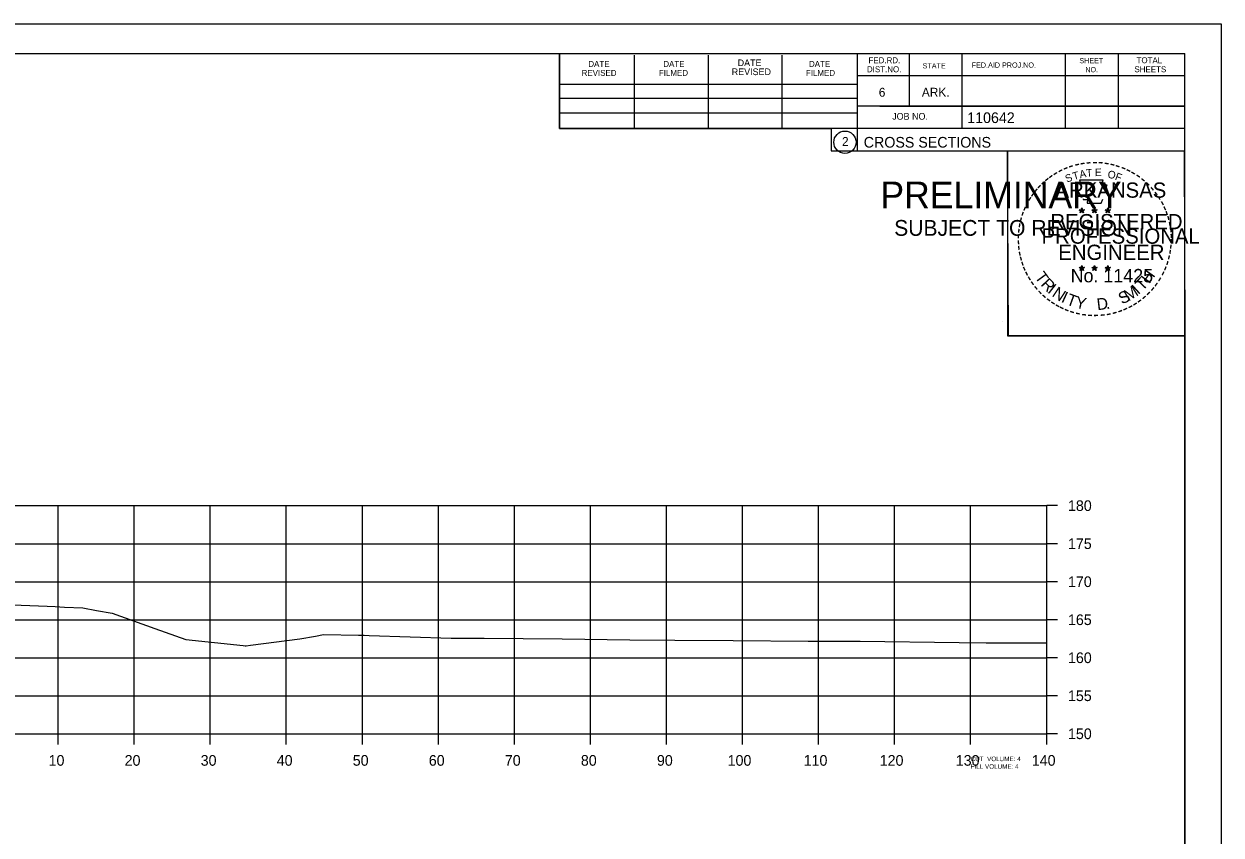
# Model space of a CAD drawing. Extents: x 1368503 to 1373085, y 379840 to 381833.
# Drawn here: x 1368678.6 to 1368836, y 381512.7 to 381619.4 of the extents above; entities that cross this region are included whole.
import ezdxf

# ---------------------------------------------------------------- set-up
doc = ezdxf.new("R2010")
doc.units = 0
for name, color, linetype in [('S_BRIDGE', 7, 'Continuous'), ('S_EDGE_PAVEMENT', 7, 'Continuous'), ('S_LANDSCAPING', 7, 'Continuous'), ('S_MISC_BOUNDARY', 7, 'Continuous'), ('S_MISC_BOUNDARY_ANNOT', 7, 'Continuous'), ('S_PHOTO_CENTERS', 7, 'Continuous'), ('S_PHOTO_NOTES', 7, 'Continuous'), ('S_TRAILS', 7, 'Continuous')]:
    doc.layers.add(name, color=color, linetype=linetype)

msp = doc.modelspace()

# ---------------------------------------------------------------- linework, layer by layer
at = {"layer": 'S_BRIDGE'}
for p, q in [((1368515.06, 381615.52), (1368831.24, 381615.52)), ((1368748.98, 381605.64), (1368748.98, 381615.52)), ((1368758.84, 381605.64), (1368758.84, 381615.32)), ((1368768.6, 381605.64), (1368768.6, 381615.32)), ((1368778.28, 381605.64), (1368778.28, 381615.32)), ((1368788.14, 381615.52), (1368788.14, 381602.72)), ((1368794.98, 381615.52), (1368794.98, 381608.58)), ((1368801.92, 381615.52), (1368801.92, 381605.64)), ((1368815.5, 381615.52), (1368815.5, 381605.64)), ((1368822.44, 381615.52), (1368822.44, 381605.64)), ((1368831.24, 381410.06), (1368831.24, 381615.52)), ((1368748.98, 381611.5), (1368788.14, 381611.5)), ((1368831.24, 381612.58), (1368788.14, 381612.58)), ((1368831.24, 381612.6), (1368831.24, 381612.6)), ((1368748.98, 381609.64), (1368788.14, 381609.64)), ((1368831.24, 381608.58), (1368788.14, 381608.58)), ((1368791.1, 381608.58), (1368831.24, 381608.58)), ((1368748.98, 381605.64), (1368748.98, 381607.7)), ((1368748.98, 381607.7), (1368788.14, 381607.7)), ((1368831.24, 381605.64), (1368748.98, 381605.64)), ((1368788.14, 381602.72), (1368831.24, 381602.72))]:
    msp.add_line(p, q, dxfattribs=at)
msp.add_circle((1368786.53, 381603.85), 1.47, dxfattribs=at)
at = {"layer": 'S_EDGE_PAVEMENT'}
for p, q in [((1368813.06, 381526.06), (1368813.06, 381556.06)), ((1368814.46, 381556.06), (1368813.06, 381556.06)), ((1368814.46, 381551.06), (1368813.06, 381551.06)), ((1368814.46, 381546.06), (1368813.06, 381546.06)), ((1368814.46, 381541.06), (1368813.06, 381541.06)), ((1368814.46, 381536.06), (1368813.06, 381536.06)), ((1368814.46, 381531.06), (1368813.06, 381531.06)), ((1368533.06, 381526.06), (1368813.06, 381526.06)), ((1368683.06, 381524.66), (1368683.06, 381526.06)), ((1368693.06, 381524.66), (1368693.06, 381526.06)), ((1368703.06, 381524.66), (1368703.06, 381526.06)), ((1368713.06, 381524.66), (1368713.06, 381526.06)), ((1368723.06, 381524.66), (1368723.06, 381526.06)), ((1368733.06, 381524.66), (1368733.06, 381526.06)), ((1368743.06, 381524.66), (1368743.06, 381526.06)), ((1368753.06, 381524.66), (1368753.06, 381526.06)), ((1368763.06, 381524.66), (1368763.06, 381526.06)), ((1368773.06, 381524.66), (1368773.06, 381526.06)), ((1368783.06, 381524.66), (1368783.06, 381526.06)), ((1368793.06, 381524.66), (1368793.06, 381526.06)), ((1368803.06, 381524.66), (1368803.06, 381526.06)), ((1368813.06, 381524.66), (1368813.06, 381526.06)), ((1368814.46, 381526.06), (1368813.06, 381526.06))]:
    msp.add_line(p, q, dxfattribs=at)
at = {"layer": 'S_LANDSCAPING'}
for p, q in [((1368817.32, 381594.97), (1368817.67, 381594.86)), ((1368817.32, 381594.97), (1368817.58, 381594.93)), ((1368817.32, 381594.97), (1368817.56, 381594.85)), ((1368817.46, 381594.56), (1368817.67, 381594.86)), ((1368817.46, 381594.56), (1368817.58, 381594.81)), ((1368817.46, 381594.56), (1368817.67, 381594.78)), ((1368817.67, 381595.23), (1368817.63, 381594.97)), ((1368817.67, 381594.86), (1368817.67, 381595.23)), ((1368817.67, 381595.23), (1368817.72, 381594.98)), ((1368818.02, 381594.97), (1368817.67, 381594.86)), ((1368817.89, 381594.56), (1368817.67, 381594.86)), ((1368817.89, 381594.56), (1368817.67, 381594.78)), ((1368818.02, 381594.97), (1368817.73, 381594.92)), ((1368817.89, 381594.56), (1368817.75, 381594.85)), ((1368818.02, 381594.97), (1368817.82, 381594.87)), ((1368818.99, 381594.97), (1368819.34, 381594.86)), ((1368818.99, 381594.97), (1368819.25, 381594.93)), ((1368818.99, 381594.97), (1368819.23, 381594.85)), ((1368819.13, 381594.56), (1368819.34, 381594.86)), ((1368819.13, 381594.56), (1368819.25, 381594.81)), ((1368819.13, 381594.56), (1368819.34, 381594.78)), ((1368819.34, 381595.23), (1368819.3, 381594.97)), ((1368819.34, 381594.86), (1368819.34, 381595.23)), ((1368819.34, 381595.23), (1368819.39, 381594.98)), ((1368819.69, 381594.97), (1368819.34, 381594.86)), ((1368819.56, 381594.56), (1368819.34, 381594.86)), ((1368819.56, 381594.56), (1368819.34, 381594.78)), ((1368819.69, 381594.97), (1368819.4, 381594.92)), ((1368819.56, 381594.56), (1368819.42, 381594.85)), ((1368819.69, 381594.97), (1368819.49, 381594.87)), ((1368820.76, 381594.96), (1368821.11, 381594.85)), ((1368820.76, 381594.96), (1368821.01, 381594.91)), ((1368820.76, 381594.96), (1368820.99, 381594.84)), ((1368820.89, 381594.55), (1368821.11, 381594.85)), ((1368820.89, 381594.55), (1368821.02, 381594.8)), ((1368820.89, 381594.55), (1368821.1, 381594.77)), ((1368821.11, 381595.21), (1368821.07, 381594.96)), ((1368821.32, 381594.55), (1368821.1, 381594.77)), ((1368821.11, 381594.85), (1368821.11, 381595.21)), ((1368821.11, 381595.21), (1368821.16, 381594.96)), ((1368821.45, 381594.96), (1368821.11, 381594.85)), ((1368821.32, 381594.55), (1368821.11, 381594.85)), ((1368821.45, 381594.96), (1368821.17, 381594.91)), ((1368821.32, 381594.55), (1368821.18, 381594.84)), ((1368821.45, 381594.96), (1368821.25, 381594.86)), ((1368817.32, 381587.4), (1368817.67, 381587.29)), ((1368817.32, 381587.4), (1368817.57, 381587.35)), ((1368817.32, 381587.4), (1368817.56, 381587.28)), ((1368817.45, 381586.99), (1368817.67, 381587.29)), ((1368817.45, 381586.99), (1368817.58, 381587.23)), ((1368817.45, 381586.99), (1368817.67, 381587.21)), ((1368817.67, 381587.65), (1368817.63, 381587.4)), ((1368817.67, 381587.29), (1368817.67, 381587.65)), ((1368817.67, 381587.65), (1368817.72, 381587.4)), ((1368818.02, 381587.4), (1368817.67, 381587.29)), ((1368817.88, 381586.99), (1368817.67, 381587.29)), ((1368817.88, 381586.99), (1368817.67, 381587.2)), ((1368818.02, 381587.4), (1368817.73, 381587.35)), ((1368817.88, 381586.99), (1368817.74, 381587.28)), ((1368818.02, 381587.4), (1368817.81, 381587.3)), ((1368818.99, 381587.4), (1368819.34, 381587.29)), ((1368818.99, 381587.4), (1368819.24, 381587.35)), ((1368818.99, 381587.4), (1368819.23, 381587.28)), ((1368819.12, 381586.99), (1368819.34, 381587.29)), ((1368819.12, 381586.99), (1368819.25, 381587.23)), ((1368819.12, 381586.99), (1368819.34, 381587.21)), ((1368819.34, 381587.65), (1368819.3, 381587.4)), ((1368819.34, 381587.29), (1368819.34, 381587.65)), ((1368819.34, 381587.65), (1368819.39, 381587.4)), ((1368819.68, 381587.4), (1368819.34, 381587.29)), ((1368819.55, 381586.99), (1368819.34, 381587.29)), ((1368819.55, 381586.99), (1368819.34, 381587.2)), ((1368819.68, 381587.4), (1368819.4, 381587.35)), ((1368819.55, 381586.99), (1368819.41, 381587.28)), ((1368819.68, 381587.4), (1368819.48, 381587.3)), ((1368820.76, 381587.39), (1368821.1, 381587.28)), ((1368820.76, 381587.39), (1368821.01, 381587.34)), ((1368820.76, 381587.39), (1368820.99, 381587.27)), ((1368820.89, 381586.98), (1368821.1, 381587.28)), ((1368820.89, 381586.98), (1368821.01, 381587.22)), ((1368820.89, 381586.98), (1368821.1, 381587.2)), ((1368821.1, 381587.64), (1368821.06, 381587.39)), ((1368821.1, 381587.28), (1368821.1, 381587.64)), ((1368821.1, 381587.64), (1368821.15, 381587.39)), ((1368821.45, 381587.39), (1368821.1, 381587.28)), ((1368821.32, 381586.98), (1368821.1, 381587.28)), ((1368821.32, 381586.98), (1368821.1, 381587.19)), ((1368821.45, 381587.39), (1368821.17, 381587.34)), ((1368821.32, 381586.98), (1368821.18, 381587.27)), ((1368821.45, 381587.39), (1368821.25, 381587.29))]:
    msp.add_line(p, q, dxfattribs=at)
for points in [[(1368817.36, 381598.85), (1368817.63, 381598.02)], [(1368820.88, 381597.93), (1368821.02, 381598.21), (1368820.33, 381598.19), (1368820.48, 381598.85), (1368817.36, 381598.85)], [(1368817.86, 381596.43), (1368817.86, 381596.34), (1368818.42, 381596.32), (1368818.37, 381595.85), (1368820.24, 381595.85), (1368820.44, 381596.38)], [(1368817.67, 381595.23), (1368817.89, 381594.56), (1368817.32, 381594.97), (1368818.02, 381594.97), (1368817.46, 381594.56), (1368817.67, 381595.23)], [(1368819.34, 381595.23), (1368819.56, 381594.56), (1368818.99, 381594.97), (1368819.69, 381594.97), (1368819.13, 381594.56), (1368819.34, 381595.23)], [(1368821.11, 381595.21), (1368821.32, 381594.55), (1368820.76, 381594.96), (1368821.45, 381594.96), (1368820.89, 381594.55), (1368821.11, 381595.21)], [(1368817.67, 381587.65), (1368817.88, 381586.99), (1368817.32, 381587.4), (1368818.02, 381587.4), (1368817.45, 381586.99), (1368817.67, 381587.65)], [(1368819.34, 381587.65), (1368819.55, 381586.99), (1368818.99, 381587.4), (1368819.68, 381587.4), (1368819.12, 381586.99), (1368819.34, 381587.65)], [(1368821.1, 381587.64), (1368821.32, 381586.98), (1368820.76, 381587.39), (1368821.45, 381587.39), (1368820.89, 381586.98), (1368821.1, 381587.64)]]:
    msp.add_lwpolyline(points, dxfattribs=at)
for centre, radius in [((1368817.67, 381594.86), 0.172), ((1368817.67, 381594.86), 0.145), ((1368817.67, 381594.86), 0.116), ((1368817.67, 381594.86), 0.0991), ((1368817.67, 381594.86), 0.0747), ((1368817.67, 381594.86), 0.0495), ((1368817.67, 381594.86), 0.0296), ((1368819.34, 381594.86), 0.172), ((1368819.34, 381594.86), 0.145), ((1368819.34, 381594.86), 0.116), ((1368819.34, 381594.86), 0.0991), ((1368819.34, 381594.86), 0.0747), ((1368819.34, 381594.86), 0.0495), ((1368819.34, 381594.86), 0.0296), ((1368821.11, 381594.85), 0.172), ((1368821.11, 381594.85), 0.145), ((1368821.11, 381594.85), 0.116), ((1368821.11, 381594.85), 0.0991), ((1368821.11, 381594.85), 0.0747), ((1368821.11, 381594.85), 0.0495), ((1368821.11, 381594.85), 0.0296), ((1368817.67, 381587.29), 0.172), ((1368817.67, 381587.29), 0.145), ((1368817.67, 381587.29), 0.116), ((1368817.67, 381587.29), 0.0991), ((1368817.67, 381587.29), 0.0747), ((1368817.67, 381587.29), 0.0495), ((1368817.67, 381587.29), 0.0296), ((1368819.34, 381587.29), 0.172), ((1368819.34, 381587.29), 0.145), ((1368819.34, 381587.29), 0.116), ((1368819.34, 381587.29), 0.0991), ((1368819.34, 381587.29), 0.0747), ((1368819.34, 381587.29), 0.0495), ((1368819.34, 381587.29), 0.0296), ((1368821.1, 381587.28), 0.172), ((1368821.1, 381587.28), 0.145), ((1368821.1, 381587.28), 0.116), ((1368821.1, 381587.28), 0.0991), ((1368821.1, 381587.28), 0.0747), ((1368821.1, 381587.28), 0.0495), ((1368821.1, 381587.28), 0.0296)]:
    msp.add_circle(centre, radius, dxfattribs=at)
at = {"layer": 'S_MISC_BOUNDARY'}
msp.add_lwpolyline([(1368673.63, 381543.17), (1368681.6, 381542.84), (1368682.66, 381542.8), (1368683.9, 381542.73), (1368686.29, 381542.63), (1368688.09, 381542.29), (1368690.15, 381541.94), (1368695.79, 381539.92), (1368699.84, 381538.47), (1368707.38, 381537.65), (1368707.63, 381537.62), (1368707.77, 381537.64), (1368708.35, 381537.71), (1368714.83, 381538.53), (1368716.92, 381538.91), (1368717.97, 381539.1), (1368722.57, 381539.02), (1368723.3, 381539.01), (1368723.98, 381538.99), (1368734.73, 381538.65), (1368739.08, 381538.65), (1368749.33, 381538.54), (1368758.25, 381538.4), (1368764.16, 381538.39), (1368771.81, 381538.32), (1368781.68, 381538.25), (1368788.53, 381538.22), (1368801.55, 381538.08), (1368805.11, 381538.04), (1368813.06, 381538.01)], dxfattribs=at)
at = {"layer": 'S_PHOTO_CENTERS'}
for p, q in [((1368533.06, 381556.06), (1368813.06, 381556.06)), ((1368683.06, 381526.06), (1368683.06, 381556.06)), ((1368693.06, 381526.06), (1368693.06, 381556.06)), ((1368703.06, 381526.06), (1368703.06, 381556.06)), ((1368713.06, 381526.06), (1368713.06, 381556.06)), ((1368723.06, 381526.06), (1368723.06, 381556.06)), ((1368733.06, 381526.06), (1368733.06, 381556.06)), ((1368743.06, 381526.06), (1368743.06, 381556.06)), ((1368753.06, 381526.06), (1368753.06, 381556.06)), ((1368763.06, 381526.06), (1368763.06, 381556.06)), ((1368773.06, 381526.06), (1368773.06, 381556.06)), ((1368783.06, 381526.06), (1368783.06, 381556.06)), ((1368793.06, 381526.06), (1368793.06, 381556.06)), ((1368803.06, 381526.06), (1368803.06, 381556.06)), ((1368813.06, 381526.06), (1368813.06, 381556.06)), ((1368533.06, 381551.06), (1368813.06, 381551.06)), ((1368533.06, 381546.06), (1368813.06, 381546.06)), ((1368533.06, 381541.06), (1368813.06, 381541.06)), ((1368533.06, 381536.06), (1368813.06, 381536.06)), ((1368533.06, 381531.06), (1368813.06, 381531.06)), ((1368533.06, 381526.06), (1368813.06, 381526.06))]:
    msp.add_line(p, q, dxfattribs=at)
at = {"layer": 'S_PHOTO_NOTES'}
for p, q in [((1368502.66, 381619.41), (1368835.99, 381619.41)), ((1368807.27, 381580.26), (1368807.27, 381580.26))]:
    msp.add_line(p, q, dxfattribs=at)
for points in [[(1368502.65, 381619.41), (1368835.99, 381619.41), (1368835.99, 381406.07), (1368502.65, 381406.07)], [(1368748.98, 381615.52), (1368748.98, 381605.64), (1368784.71, 381605.64), (1368784.71, 381602.72), (1368807.91, 381602.72), (1368807.91, 381578.38), (1368831.24, 381578.38), (1368831.24, 381410.06), (1368515.06, 381410.06), (1368515.06, 381615.52)], [(1368807.91, 381602.72), (1368831.12, 381602.72), (1368831.24, 381578.38), (1368808.03, 381578.38)]]:
    msp.add_lwpolyline(points, close=True, dxfattribs=at)

# ---------------------------------------------------------------- texts
at = {"layer": 'S_BRIDGE'}
for s, height, p in [('DATE', 0.879, (1368772.42, 381613.86)), ('FED.RD.', 0.782, (1368789.62, 381614.24)), ('SHEET', 0.684, (1368817.36, 381614.24)), ('TOTAL', 0.782, (1368824.88, 381614.24)), ('REVISED', 0.782, (1368751.9, 381612.58)), ('DATE', 0.782, (1368752.78, 381613.76)), ('FILMED', 0.782, (1368762.06, 381612.58)), ('DATE', 0.782, (1368762.64, 381613.76)), ('REVISED', 0.879, (1368771.64, 381612.68)), ('FILMED', 0.782, (1368781.4, 381612.58)), ('DATE', 0.782, (1368781.8, 381613.76)), ('DIST.NO.', 0.782, (1368789.42, 381613.06)), ('STATE', 0.684, (1368796.74, 381613.56)), ('FED.AID PROJ.NO.', 0.684, (1368803.2, 381613.66)), ('NO.', 0.684, (1368818.14, 381613.06)), ('SHEETS', 0.782, (1368824.6, 381613.06)), ('6', 1.17, (1368790.98, 381609.84)), ('ARK.', 1.172, (1368796.64, 381609.84)), ('JOB NO.', 0.879, (1368792.74, 381606.82)), ('110642', 1.4, (1368802.61, 381606.38)), ('2', 1.17, (1368786.14, 381603.37)), ('CROSS SECTIONS', 1.4, (1368789, 381603.15))]:
    msp.add_text(s, height=height, rotation=360, dxfattribs=at).set_placement(p)
at = {"layer": 'S_LANDSCAPING'}
for s, height, rotation, p in [('-', 1.6, 24.3072, (1368815.48, 381599.71)), ('-', 1.6, 19.1761, (1368816.11, 381599.98)), ('-', 1.6, 13.6301, (1368816.86, 381600.22)), ('-', 1.6, 10.2193, (1368817.54, 381600.38)), ('-', 1.6, 5.8968, (1368818.27, 381600.49)), ('-', 1.6, 0.1862, (1368819.04, 381600.56)), ('-', 1.6, 357.743, (1368819.76, 381600.55)), ('-', 1.6, 352.1617, (1368820.51, 381600.49)), ('-', 1.6, 347.2049, (1368821.23, 381600.38)), ('-', 1.6, 342.3362, (1368821.86, 381600.22)), ('-', 1.6, 337.8551, (1368822.6, 381600)), ('-', 1.6, 38.9507, (1368813.19, 381598.25)), ('-', 1.6, 36.2317, (1368813.67, 381598.63)), ('-', 1.6, 34.0636, (1368814.25, 381599.02)), ('-', 1.6, 28.7918, (1368814.85, 381599.39)), ('S', 1, 21.594, (1368815.72, 381598.53)), ('T', 1, 16.4036, (1368816.63, 381598.86)), ('A', 1, 11.2132, (1368817.46, 381599.11)), ('T', 1, 6.0228, (1368818.31, 381599.28)), ('E', 1, 0.8323, (1368819.41, 381599.39)), ('O', 1, 350.4515, (1368821.02, 381599.18)), ('F', 1, 340.0707, (1368821.97, 381598.95)), ('-', 1.6, 334.1211, (1368823.23, 381599.73)), ('-', 1.6, 329.6409, (1368823.81, 381599.45)), ('-', 1.6, 325.8627, (1368824.45, 381599.09)), ('-', 1.6, 320.5297, (1368825.06, 381598.66)), ('-', 1.6, 50.6142, (1368811.91, 381596.87)), ('-', 1.6, 48.423, (1368812.31, 381597.35)), ('-', 1.6, 42.9622, (1368812.76, 381597.83)), ('ARKANSAS', 2, 360, (1368814.22, 381596.56)), ('-', 1.6, 315.5786, (1368825.66, 381598.17)), ('-', 1.6, 309.8797, (1368826.23, 381597.62)), ('-', 1.6, 306.6522, (1368826.75, 381597.02)), ('-', 1.6, 62.8713, (1368810.86, 381595.16)), ('-', 1.6, 58.0706, (1368811.17, 381595.77)), ('-', 1.6, 54.2325, (1368811.5, 381596.3)), ('-', 1.4, 303.6753, (1368827.24, 381596.45)), ('-', 1.6, 299.6684, (1368827.56, 381595.84)), ('-', 1.6, 72.3945, (1368810.38, 381593.92)), ('-', 1.6, 67.7743, (1368810.6, 381594.55)), ('REGISTERED', 2, 360, (1368813.54, 381592.41)), ('DWB', 0.01, 360, (1368817.66, 381594.85)), ('DWB', 0.01, 360, (1368819.33, 381594.85)), ('DWB', 0.01, 360, (1368821.09, 381594.84)), ('-', 1.6, 294.6628, (1368827.88, 381595.23)), ('-', 1.6, 290.5728, (1368828.14, 381594.66)), ('-', 1.6, 285.1233, (1368828.37, 381594.08)), ('-', 1.6, 81.2013, (1368810.05, 381592.49)), ('-', 1.6, 75.461, (1368810.18, 381593.2)), ('-', 1.6, 280.5493, (1368828.57, 381593.33)), ('-', 1.6, 89.0622, (1368809.95, 381591.1)), ('-', 1.6, 85.1863, (1368809.98, 381591.8)), ('PROFESSIONAL', 2, 360, (1368812.39, 381590.51)), ('-', 1.6, 276.5962, (1368828.74, 381592.57)), ('-', 1.6, 274.3301, (1368828.8, 381591.84)), ('-', 1.6, 269.9407, (1368828.83, 381591.21)), ('-', 1.6, 94.1959, (1368809.99, 381590.37)), ('-', 1.6, 98.9479, (1368810.06, 381589.71)), ('-', 1.6, 101.7149, (1368810.19, 381588.97)), ('ENGINEER', 2, 360, (1368814.58, 381588.38)), ('-', 1.6, 260.9953, (1368828.74, 381589.89)), ('-', 1.6, 263.5172, (1368828.81, 381590.55)), ('-', 1.6, 105.4578, (1368810.36, 381588.38)), ('-', 1.6, 109.0874, (1368810.57, 381587.75)), ('-', 1.6, 252.8681, (1368828.45, 381588.49)), ('-', 1.6, 255.7626, (1368828.63, 381589.21)), ('-', 1.6, 114.0643, (1368810.82, 381587.15)), ('-', 1.6, 115.7289, (1368811.13, 381586.53)), ('T', 1.54, 306.0406, (1368811.43, 381586.13)), ('No. 11425', 1.757, 360, (1368816.21, 381585.43)), ('DWB', 0.01, 360, (1368817.66, 381587.28)), ('DWB', 0.01, 360, (1368819.33, 381587.28)), ('DWB', 0.01, 360, (1368821.09, 381587.27)), ('H', 1.54, 54.6088, (1368826.55, 381585.16)), ('-', 1.6, 244.6197, (1368827.96, 381587.19)), ('-', 1.6, 247.8887, (1368828.23, 381587.82)), ('-', 1.6, 120.4471, (1368811.49, 381585.95)), ('-', 1.6, 125.8934, (1368811.89, 381585.39)), ('-', 1.6, 130.7181, (1368812.35, 381584.83)), ('R', 1.54, 314.005, (1368812.19, 381585.08)), ('I', 1.54, 321.9694, (1368813.09, 381584.15)), ('N', 1.54, 326.5002, (1368813.66, 381583.67)), ('M', 1.54, 32.6563, (1368823.81, 381582.89)), ('I', 1.54, 42.1136, (1368825.1, 381583.74)), ('T', 1.54, 46.6444, (1368825.66, 381584.22)), ('-', 1.6, 231.2538, (1368826.74, 381585.22)), ('-', 1.6, 233.8452, (1368827.17, 381585.79)), ('-', 1.6, 239.0712, (1368827.57, 381586.44)), ('-', 1.6, 134.2238, (1368812.87, 381584.29)), ('-', 1.6, 138.9338, (1368813.39, 381583.83)), ('-', 1.6, 144.6463, (1368813.95, 381583.42)), ('I', 1.54, 335.3603, (1368814.87, 381582.89)), ('T', 1.54, 339.8912, (1368815.53, 381582.56)), ('Y', 1.54, 347.8556, (1368816.74, 381582.12)), ('D', 1.54, 6.3969, (1368819.73, 381581.76)), ('S', 1.54, 26.9312, (1368822.97, 381582.49)), ('-', 1.6, 215.7363, (1368825.19, 381583.68)), ('-', 1.6, 221.0851, (1368825.74, 381584.15)), ('-', 1.6, 225.7653, (1368826.26, 381584.66)), ('-', 1.6, 148.0898, (1368814.51, 381583.05)), ('-', 1.6, 151.5704, (1368815.09, 381582.72)), ('-', 1.6, 154.6002, (1368815.61, 381582.48)), ('-', 1.6, 158.5612, (1368816.24, 381582.22)), ('-', 1.6, 162.7983, (1368816.92, 381582.01)), ('.', 1.54, 13.7642, (1368820.92, 381581.88)), ('-', 1.6, 195.4743, (1368822.18, 381582.11)), ('-', 1.6, 200.7184, (1368822.85, 381582.35)), ('-', 1.6, 204.2516, (1368823.47, 381582.62)), ('-', 1.6, 207.3568, (1368824.1, 381582.94)), ('-', 1.6, 212.2491, (1368824.65, 381583.29)), ('-', 1.6, 167.5555, (1368817.64, 381581.85)), ('-', 1.6, 173.1155, (1368818.41, 381581.74)), ('-', 1.6, 176.5183, (1368819.16, 381581.68)), ('-', 1.6, 181.5918, (1368819.9, 381581.7)), ('-', 1.6, 185.8167, (1368820.71, 381581.78)), ('-', 1.6, 191.2858, (1368821.45, 381581.91))]:
    msp.add_text(s, height=height, rotation=rotation, dxfattribs=at).set_placement(p)
at = {"layer": 'S_MISC_BOUNDARY_ANNOT'}
for s, height, p in [('PRELIMINARY', 3.5, (1368791.19, 381595.18)), ('DWB', 0.01, (1368791.94, 381597.03)), ('SUBJECT TO REVISION', 2.0751, (1368793, 381591.55))]:
    msp.add_text(s, height=height, rotation=360, dxfattribs=at).set_placement(p)
at = {"layer": 'S_TRAILS'}
for s, height, p in [('180', 1.4, (1368815.86, 381555.36)), ('175', 1.4, (1368815.86, 381550.36)), ('170', 1.4, (1368815.86, 381545.36)), ('165', 1.4, (1368815.86, 381540.36)), ('160', 1.4, (1368815.86, 381535.36)), ('155', 1.4, (1368815.86, 381530.36)), ('150', 1.4, (1368815.86, 381525.36)), ('10', 1.4, (1368681.8, 381521.86)), ('20', 1.4, (1368691.8, 381521.86)), ('30', 1.4, (1368701.8, 381521.86)), ('40', 1.4, (1368711.8, 381521.86)), ('50', 1.4, (1368721.8, 381521.86)), ('60', 1.4, (1368731.8, 381521.86)), ('70', 1.4, (1368741.8, 381521.86)), ('80', 1.4, (1368751.8, 381521.86)), ('90', 1.4, (1368761.8, 381521.86)), ('100', 1.4, (1368771.1, 381521.86)), ('110', 1.4, (1368781.1, 381521.86)), ('120', 1.4, (1368791.1, 381521.86)), ('130', 1.4, (1368801.1, 381521.86)), ('CUT  VOLUME: 4', 0.6, (1368803.06, 381522.46)), ('FILL VOLUME: 4', 0.6, (1368803.06, 381521.46)), ('140', 1.4, (1368811.1, 381521.86))]:
    msp.add_text(s, height=height, dxfattribs=at).set_placement(p)

doc.saveas('drawing.dxf')
